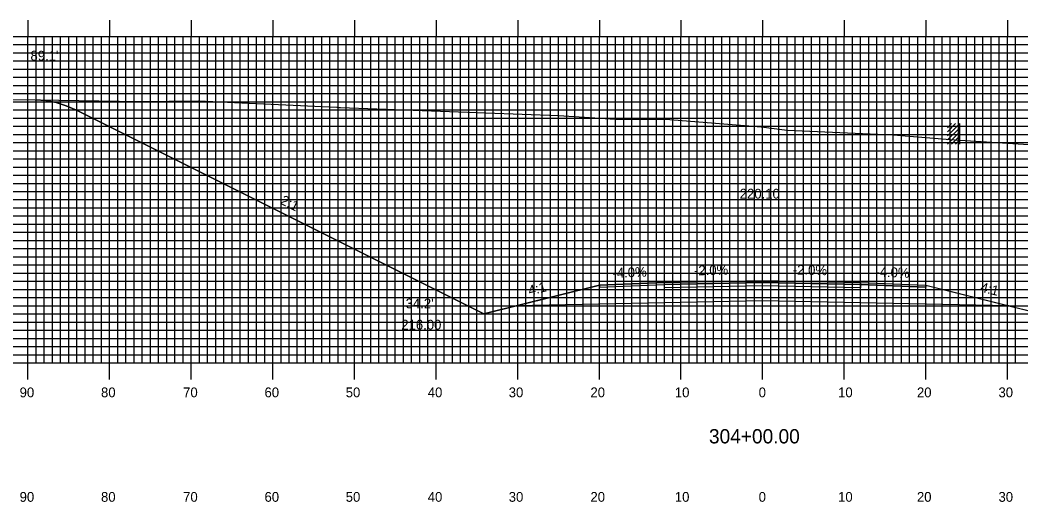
# Model space of a CAD drawing. Extents: x 1816489 to 1816833, y 442591 to 442811.
# Drawn here: x 1816564.1 to 1816686.7, y 442656.6 to 442715.7 of the extents above; entities that cross this region are included whole.
import ezdxf

# ---------------------------------------------------------------- set-up
doc = ezdxf.new("R2010")
doc.units = 0
for name, color, linetype in [('ANNOTATION', 7, 'Continuous'), ('D_Roadway_Centerline', 7, 'Continuous'), ('D_Roadway_Centerline_Text', 7, 'Continuous'), ('D_Roadway_Edge_Shoulder', 7, 'Continuous'), ('D_Roadway_Edge_TW', 7, 'Continuous'), ('D_Roadway_Pavement', 7, 'Continuous'), ('D_Roadway_SlopeLines', 7, 'Continuous'), ('D_Roadway_SubGrade', 7, 'Continuous'), ('D_Text_Standard', 7, 'Continuous'), ('H_V ANNOTATION', 7, 'Continuous'), ('M_Buildings_Rooftop', 7, 'Continuous'), ('MAJOR', 7, 'Continuous'), ('MINOR', 7, 'Continuous'), ('PDRAIN', 7, 'Continuous'), ('S_Roadway_Centerline', 7, 'Continuous')]:
    doc.layers.add(name, color=color, linetype=linetype)

msp = doc.modelspace()

# ---------------------------------------------------------------- linework, layer by layer
at = {"layer": 'D_Roadway_Centerline'}
msp.add_lwpolyline([(1816566.01, 442705.89), (1816567.26, 442705.8), (1816568.51, 442705.55), (1816569.76, 442705.16), (1816571.01, 442704.61), (1816620.9, 442679.67), (1816624.9, 442680.67), (1816635.07, 442683.21), (1816643.07, 442683.53), (1816655.07, 442683.77), (1816667.07, 442683.53), (1816675.07, 442683.21), (1816685.25, 442680.67), (1816689.25, 442679.67), (1816723.34, 442696.71), (1816724.59, 442697.25), (1816725.84, 442697.6), (1816727.09, 442697.77), (1816728.34, 442697.76)], dxfattribs=at)
at = {"layer": 'D_Roadway_Edge_Shoulder'}
for points in [[(1816643.07, 442683.53), (1816635.07, 442683.21), (1816635.07, 442682.96), (1816643.07, 442683.28)], [(1816667.07, 442683.53), (1816675.07, 442683.21), (1816675.07, 442682.96), (1816667.07, 442683.28)]]:
    msp.add_lwpolyline(points, close=True, dxfattribs=at)
at = {"layer": 'D_Roadway_Edge_TW'}
msp.add_lwpolyline([(1816643.07, 442683.28), (1816643.07, 442683.53), (1816655.07, 442683.77), (1816667.07, 442683.53), (1816667.07, 442683.28), (1816655.07, 442683.52)], close=True, dxfattribs=at)
at = {"layer": 'D_Roadway_Pavement'}
msp.add_lwpolyline([(1816643.07, 442682.86), (1816643.07, 442683.28), (1816655.07, 442683.52), (1816667.07, 442683.28), (1816667.07, 442682.86), (1816655.07, 442683.1)], close=True, dxfattribs=at)
at = {"layer": 'D_Roadway_SlopeLines'}
for points in [[(1816620.9, 442679.67), (1816571.01, 442704.61), (1816569.76, 442705.16), (1816568.51, 442705.55), (1816567.26, 442705.8), (1816566.01, 442705.89)], [(1816635.07, 442683.21), (1816620.9, 442679.67)], [(1816675.07, 442683.21), (1816689.25, 442679.67)]]:
    msp.add_lwpolyline(points, dxfattribs=at)
at = {"layer": 'D_Roadway_SubGrade'}
msp.add_lwpolyline([(1816643.07, 442681.03), (1816624.9, 442680.67), (1816635.07, 442683.21), (1816635.07, 442682.96), (1816643.07, 442683.28), (1816655.07, 442683.52), (1816667.07, 442683.28), (1816675.07, 442682.96), (1816675.07, 442683.21), (1816685.25, 442680.67), (1816667.07, 442681.03), (1816655.07, 442681.27)], close=True, dxfattribs=at)
at = {"layer": 'M_Buildings_Rooftop'}
for p, q in [((1816677.71, 442701.48), (1816679.22, 442702.99)), ((1816677.71, 442701.97), (1816678.69, 442702.99)), ((1816677.71, 442702.46), (1816678.2, 442702.99)), ((1816679.22, 442700.46), (1816679.22, 442702.99)), ((1816677.71, 442700.98), (1816679.22, 442702.46)), ((1816677.71, 442700.46), (1816679.22, 442701.97)), ((1816678.2, 442700.46), (1816679.22, 442701.48)), ((1816678.69, 442700.46), (1816679.22, 442700.98))]:
    msp.add_line(p, q, dxfattribs=at)
at = {"layer": 'MAJOR'}
for p, q in [((1816565.07, 442715.67), (1816565.07, 442713.67)), ((1816575.07, 442715.67), (1816575.07, 442713.67)), ((1816585.07, 442715.67), (1816585.07, 442713.67)), ((1816595.07, 442715.67), (1816595.07, 442713.67)), ((1816605.07, 442715.67), (1816605.07, 442713.67)), ((1816615.07, 442715.67), (1816615.07, 442713.67)), ((1816625.07, 442715.67), (1816625.07, 442713.67)), ((1816635.07, 442715.67), (1816635.07, 442713.67)), ((1816645.07, 442715.67), (1816645.07, 442713.67)), ((1816655.07, 442715.67), (1816655.07, 442713.67)), ((1816665.07, 442715.67), (1816665.07, 442713.67)), ((1816675.07, 442715.67), (1816675.07, 442713.67)), ((1816685.07, 442715.67), (1816685.07, 442713.67)), ((1816515.07, 442713.67), (1816795.07, 442713.67)), ((1816515.07, 442713.67), (1816795.07, 442713.67)), ((1816565.07, 442673.67), (1816565.07, 442713.67)), ((1816575.07, 442673.67), (1816575.07, 442713.67)), ((1816585.07, 442673.67), (1816585.07, 442713.67)), ((1816595.07, 442673.67), (1816595.07, 442713.67)), ((1816605.07, 442673.67), (1816605.07, 442713.67)), ((1816615.07, 442673.67), (1816615.07, 442713.67)), ((1816625.07, 442673.67), (1816625.07, 442713.67)), ((1816635.07, 442673.67), (1816635.07, 442713.67)), ((1816645.07, 442673.67), (1816645.07, 442713.67)), ((1816655.07, 442673.67), (1816655.07, 442713.67)), ((1816665.07, 442673.67), (1816665.07, 442713.67)), ((1816675.07, 442673.67), (1816675.07, 442713.67)), ((1816685.07, 442673.67), (1816685.07, 442713.67)), ((1816515.07, 442708.67), (1816795.07, 442708.67)), ((1816515.07, 442703.67), (1816795.07, 442703.67)), ((1816515.07, 442698.67), (1816795.07, 442698.67)), ((1816515.07, 442693.67), (1816795.07, 442693.67)), ((1816515.07, 442688.67), (1816795.07, 442688.67)), ((1816515.07, 442683.67), (1816795.07, 442683.67)), ((1816515.07, 442678.67), (1816795.07, 442678.67)), ((1816515.07, 442673.67), (1816795.07, 442673.67)), ((1816515.07, 442673.67), (1816795.07, 442673.67)), ((1816565.07, 442671.66), (1816565.07, 442673.67)), ((1816575.07, 442671.66), (1816575.07, 442673.67)), ((1816585.07, 442671.66), (1816585.07, 442673.67)), ((1816595.07, 442671.66), (1816595.07, 442673.67)), ((1816605.07, 442671.66), (1816605.07, 442673.67)), ((1816615.07, 442671.66), (1816615.07, 442673.67)), ((1816625.07, 442671.66), (1816625.07, 442673.67)), ((1816635.07, 442671.66), (1816635.07, 442673.67)), ((1816645.07, 442671.66), (1816645.07, 442673.67)), ((1816655.07, 442671.66), (1816655.07, 442673.67)), ((1816665.07, 442671.66), (1816665.07, 442673.67)), ((1816675.07, 442671.66), (1816675.07, 442673.67)), ((1816685.07, 442671.66), (1816685.07, 442673.67))]:
    msp.add_line(p, q, dxfattribs=at)
at = {"layer": 'MINOR'}
for p, q in [((1816515.07, 442712.67), (1816795.07, 442712.67)), ((1816566.07, 442673.67), (1816566.07, 442713.67)), ((1816567.07, 442673.67), (1816567.07, 442713.67)), ((1816568.07, 442673.67), (1816568.07, 442713.67)), ((1816569.07, 442673.67), (1816569.07, 442713.67)), ((1816570.07, 442673.67), (1816570.07, 442713.67)), ((1816571.07, 442673.67), (1816571.07, 442713.67)), ((1816572.07, 442673.67), (1816572.07, 442713.67)), ((1816573.07, 442673.67), (1816573.07, 442713.67)), ((1816574.07, 442673.67), (1816574.07, 442713.67)), ((1816576.07, 442673.67), (1816576.07, 442713.67)), ((1816577.07, 442673.67), (1816577.07, 442713.67)), ((1816578.07, 442673.67), (1816578.07, 442713.67)), ((1816579.07, 442673.67), (1816579.07, 442713.67)), ((1816580.07, 442673.67), (1816580.07, 442713.67)), ((1816581.07, 442673.67), (1816581.07, 442713.67)), ((1816582.07, 442673.67), (1816582.07, 442713.67)), ((1816583.07, 442673.67), (1816583.07, 442713.67)), ((1816584.07, 442673.67), (1816584.07, 442713.67)), ((1816586.07, 442673.67), (1816586.07, 442713.67)), ((1816587.07, 442673.67), (1816587.07, 442713.67)), ((1816588.07, 442673.67), (1816588.07, 442713.67)), ((1816589.07, 442673.67), (1816589.07, 442713.67)), ((1816590.07, 442673.67), (1816590.07, 442713.67)), ((1816591.07, 442673.67), (1816591.07, 442713.67)), ((1816592.07, 442673.67), (1816592.07, 442713.67)), ((1816593.07, 442673.67), (1816593.07, 442713.67)), ((1816594.07, 442673.67), (1816594.07, 442713.67)), ((1816596.07, 442673.67), (1816596.07, 442713.67)), ((1816597.07, 442673.67), (1816597.07, 442713.67)), ((1816598.07, 442673.67), (1816598.07, 442713.67)), ((1816599.07, 442673.67), (1816599.07, 442713.67)), ((1816600.07, 442673.67), (1816600.07, 442713.67)), ((1816601.07, 442673.67), (1816601.07, 442713.67)), ((1816602.07, 442673.67), (1816602.07, 442713.67)), ((1816603.07, 442673.67), (1816603.07, 442713.67)), ((1816604.07, 442673.67), (1816604.07, 442713.67)), ((1816606.07, 442673.67), (1816606.07, 442713.67)), ((1816607.07, 442673.67), (1816607.07, 442713.67)), ((1816608.07, 442673.67), (1816608.07, 442713.67)), ((1816609.07, 442673.67), (1816609.07, 442713.67)), ((1816610.07, 442673.67), (1816610.07, 442713.67)), ((1816611.07, 442673.67), (1816611.07, 442713.67)), ((1816612.07, 442673.67), (1816612.07, 442713.67)), ((1816613.07, 442673.67), (1816613.07, 442713.67)), ((1816614.07, 442673.67), (1816614.07, 442713.67)), ((1816616.07, 442673.67), (1816616.07, 442713.67)), ((1816617.07, 442673.67), (1816617.07, 442713.67)), ((1816618.07, 442673.67), (1816618.07, 442713.67)), ((1816619.07, 442673.67), (1816619.07, 442713.67)), ((1816620.07, 442673.67), (1816620.07, 442713.67)), ((1816621.07, 442673.67), (1816621.07, 442713.67)), ((1816622.07, 442673.67), (1816622.07, 442713.67)), ((1816623.07, 442673.67), (1816623.07, 442713.67)), ((1816624.07, 442673.67), (1816624.07, 442713.67)), ((1816626.07, 442673.67), (1816626.07, 442713.67)), ((1816627.07, 442673.67), (1816627.07, 442713.67)), ((1816628.07, 442673.67), (1816628.07, 442713.67)), ((1816629.07, 442673.67), (1816629.07, 442713.67)), ((1816630.07, 442673.67), (1816630.07, 442713.67)), ((1816631.07, 442673.67), (1816631.07, 442713.67)), ((1816632.07, 442673.67), (1816632.07, 442713.67)), ((1816633.07, 442673.67), (1816633.07, 442713.67)), ((1816634.07, 442673.67), (1816634.07, 442713.67)), ((1816636.07, 442673.67), (1816636.07, 442713.67)), ((1816637.07, 442673.67), (1816637.07, 442713.67)), ((1816638.07, 442673.67), (1816638.07, 442713.67)), ((1816639.07, 442673.67), (1816639.07, 442713.67)), ((1816640.07, 442673.67), (1816640.07, 442713.67)), ((1816641.07, 442673.67), (1816641.07, 442713.67)), ((1816642.07, 442673.67), (1816642.07, 442713.67)), ((1816643.07, 442673.67), (1816643.07, 442713.67)), ((1816644.07, 442673.67), (1816644.07, 442713.67)), ((1816646.07, 442673.67), (1816646.07, 442713.67)), ((1816647.07, 442673.67), (1816647.07, 442713.67)), ((1816648.07, 442673.67), (1816648.07, 442713.67)), ((1816649.07, 442673.67), (1816649.07, 442713.67)), ((1816650.07, 442673.67), (1816650.07, 442713.67)), ((1816651.07, 442673.67), (1816651.07, 442713.67)), ((1816652.07, 442673.67), (1816652.07, 442713.67)), ((1816653.07, 442673.67), (1816653.07, 442713.67)), ((1816654.07, 442673.67), (1816654.07, 442713.67)), ((1816656.07, 442673.67), (1816656.07, 442713.67)), ((1816657.07, 442673.67), (1816657.07, 442713.67)), ((1816658.07, 442673.67), (1816658.07, 442713.67)), ((1816659.07, 442673.67), (1816659.07, 442713.67)), ((1816660.07, 442673.67), (1816660.07, 442713.67)), ((1816661.07, 442673.67), (1816661.07, 442713.67)), ((1816662.07, 442673.67), (1816662.07, 442713.67)), ((1816663.07, 442673.67), (1816663.07, 442713.67)), ((1816664.07, 442673.67), (1816664.07, 442713.67)), ((1816666.07, 442673.67), (1816666.07, 442713.67)), ((1816667.07, 442673.67), (1816667.07, 442713.67)), ((1816668.07, 442673.67), (1816668.07, 442713.67)), ((1816669.07, 442673.67), (1816669.07, 442713.67)), ((1816670.07, 442673.67), (1816670.07, 442713.67)), ((1816671.07, 442673.67), (1816671.07, 442713.67)), ((1816672.07, 442673.67), (1816672.07, 442713.67)), ((1816673.07, 442673.67), (1816673.07, 442713.67)), ((1816674.07, 442673.67), (1816674.07, 442713.67)), ((1816676.07, 442673.67), (1816676.07, 442713.67)), ((1816677.07, 442673.67), (1816677.07, 442713.67)), ((1816678.07, 442673.67), (1816678.07, 442713.67)), ((1816679.07, 442673.67), (1816679.07, 442713.67)), ((1816680.07, 442673.67), (1816680.07, 442713.67)), ((1816681.07, 442673.67), (1816681.07, 442713.67)), ((1816682.07, 442673.67), (1816682.07, 442713.67)), ((1816683.07, 442673.67), (1816683.07, 442713.67)), ((1816684.07, 442673.67), (1816684.07, 442713.67)), ((1816686.07, 442673.67), (1816686.07, 442713.67)), ((1816515.07, 442711.67), (1816795.07, 442711.67)), ((1816515.07, 442710.67), (1816795.07, 442710.67)), ((1816515.07, 442709.67), (1816795.07, 442709.67)), ((1816515.07, 442707.67), (1816795.07, 442707.67)), ((1816515.07, 442706.67), (1816795.07, 442706.67)), ((1816515.07, 442705.67), (1816795.07, 442705.67)), ((1816515.07, 442704.67), (1816795.07, 442704.67)), ((1816515.07, 442702.67), (1816795.07, 442702.67)), ((1816515.07, 442701.67), (1816795.07, 442701.67)), ((1816515.07, 442700.67), (1816795.07, 442700.67)), ((1816515.07, 442699.67), (1816795.07, 442699.67)), ((1816515.07, 442697.67), (1816795.07, 442697.67)), ((1816515.07, 442696.67), (1816795.07, 442696.67)), ((1816515.07, 442695.67), (1816795.07, 442695.67)), ((1816515.07, 442694.67), (1816795.07, 442694.67)), ((1816515.07, 442692.67), (1816795.07, 442692.67)), ((1816515.07, 442691.67), (1816795.07, 442691.67)), ((1816515.07, 442690.67), (1816795.07, 442690.67)), ((1816515.07, 442689.67), (1816795.07, 442689.67)), ((1816515.07, 442687.67), (1816795.07, 442687.67)), ((1816515.07, 442686.67), (1816795.07, 442686.67)), ((1816515.07, 442685.67), (1816795.07, 442685.67)), ((1816515.07, 442684.67), (1816795.07, 442684.67)), ((1816515.07, 442682.67), (1816795.07, 442682.67)), ((1816515.07, 442681.67), (1816795.07, 442681.67)), ((1816515.07, 442680.67), (1816795.07, 442680.67)), ((1816515.07, 442679.67), (1816795.07, 442679.67)), ((1816515.07, 442677.67), (1816795.07, 442677.67)), ((1816515.07, 442676.67), (1816795.07, 442676.67)), ((1816515.07, 442675.67), (1816795.07, 442675.67)), ((1816515.07, 442674.67), (1816795.07, 442674.67))]:
    msp.add_line(p, q, dxfattribs=at)
at = {"layer": 'PDRAIN'}
msp.add_line((1816610.18, 442679.67), (1816620.9, 442679.67), dxfattribs=at)
at = {"layer": 'S_Roadway_Centerline'}
msp.add_lwpolyline([(1816515.07, 442707.12), (1816518.07, 442707.07), (1816534.11, 442706.67), (1816534.8, 442706.64), (1816535.11, 442706.64), (1816552.94, 442706.26), (1816563.02, 442705.93), (1816568.85, 442705.86), (1816578.69, 442705.68), (1816585.91, 442705.77), (1816602.93, 442704.98), (1816603.04, 442704.97), (1816603.11, 442704.97), (1816603.35, 442704.96), (1816630.05, 442703.98), (1816637.06, 442703.54), (1816643.69, 442703.48), (1816654.89, 442702.57), (1816658.1, 442702.19), (1816668.23, 442701.75), (1816671.11, 442701.59), (1816672.06, 442701.54), (1816678.58, 442701.01), (1816690.94, 442700.24)], dxfattribs=at)

# ---------------------------------------------------------------- texts
at = {"layer": 'ANNOTATION'}
for s, rotation, p in [('2:1', 333.4349, (1816595.89, 442693.21)), ('-2.0%', 1.1458, (1816646.68, 442684.4)), ('-2.0%', 358.8542, (1816658.76, 442684.5)), ('-4.0%', 2.2906, (1816636.7, 442684.08)), ('-4.0%', 357.7094, (1816668.86, 442684.26)), ('4:1', 14.0362, (1816626.52, 442681.93)), ('4:1', 345.9638, (1816681.67, 442682.42))]:
    msp.add_text(s, height=1.2, rotation=rotation, dxfattribs=at).set_placement(p)
for s, p in [("34.2'", (1816611.34, 442680.36)), ('216.00', (1816610.81, 442677.76))]:
    msp.add_text(s, height=1.2, dxfattribs=at).set_placement(p)
at = {"layer": 'D_Roadway_Centerline'}
for s, p in [('C', (1816655.07, 442683.77)), ('L', (1816655.07, 442683.76))]:
    msp.add_text(s, height=0.0146, dxfattribs=at).set_placement(p)
at = {"layer": 'D_Roadway_Centerline_Text'}
msp.add_text('220.10', height=1.2, dxfattribs=at).set_placement((1816652.27, 442693.8))
at = {"layer": 'D_Text_Standard'}
msp.add_text("89.1'", height=1.2, dxfattribs=at).set_placement((1816565.38, 442710.7))
at = {"layer": 'H_V ANNOTATION'}
for s, height, p in [('90', 1.2, (1816564.05, 442669.47)), ('80', 1.2, (1816574.02, 442669.47)), ('70', 1.2, (1816584.08, 442669.47)), ('60', 1.2, (1816594.05, 442669.47)), ('50', 1.2, (1816604, 442669.47)), ('40', 1.2, (1816614.05, 442669.47)), ('30', 1.2, (1816623.97, 442669.47)), ('20', 1.2, (1816633.98, 442669.47)), ('10', 1.2, (1816644.32, 442669.47)), ('0', 1.2, (1816654.59, 442669.47)), ('10', 1.2, (1816664.32, 442669.47)), ('20', 1.2, (1816673.98, 442669.47)), ('30', 1.2, (1816683.97, 442669.47)), ('304+00.00', 1.75, (1816648.5, 442663.82)), ('90', 1.2, (1816564.05, 442656.67)), ('80', 1.2, (1816574.02, 442656.67)), ('70', 1.2, (1816584.08, 442656.67)), ('60', 1.2, (1816594.05, 442656.67)), ('50', 1.2, (1816604, 442656.67)), ('40', 1.2, (1816614.05, 442656.67)), ('30', 1.2, (1816623.97, 442656.67)), ('20', 1.2, (1816633.98, 442656.67)), ('10', 1.2, (1816644.32, 442656.67)), ('0', 1.2, (1816654.59, 442656.67)), ('10', 1.2, (1816664.32, 442656.67)), ('20', 1.2, (1816673.98, 442656.67)), ('30', 1.2, (1816683.97, 442656.67))]:
    msp.add_text(s, height=height, dxfattribs=at).set_placement(p)

doc.saveas('drawing.dxf')
